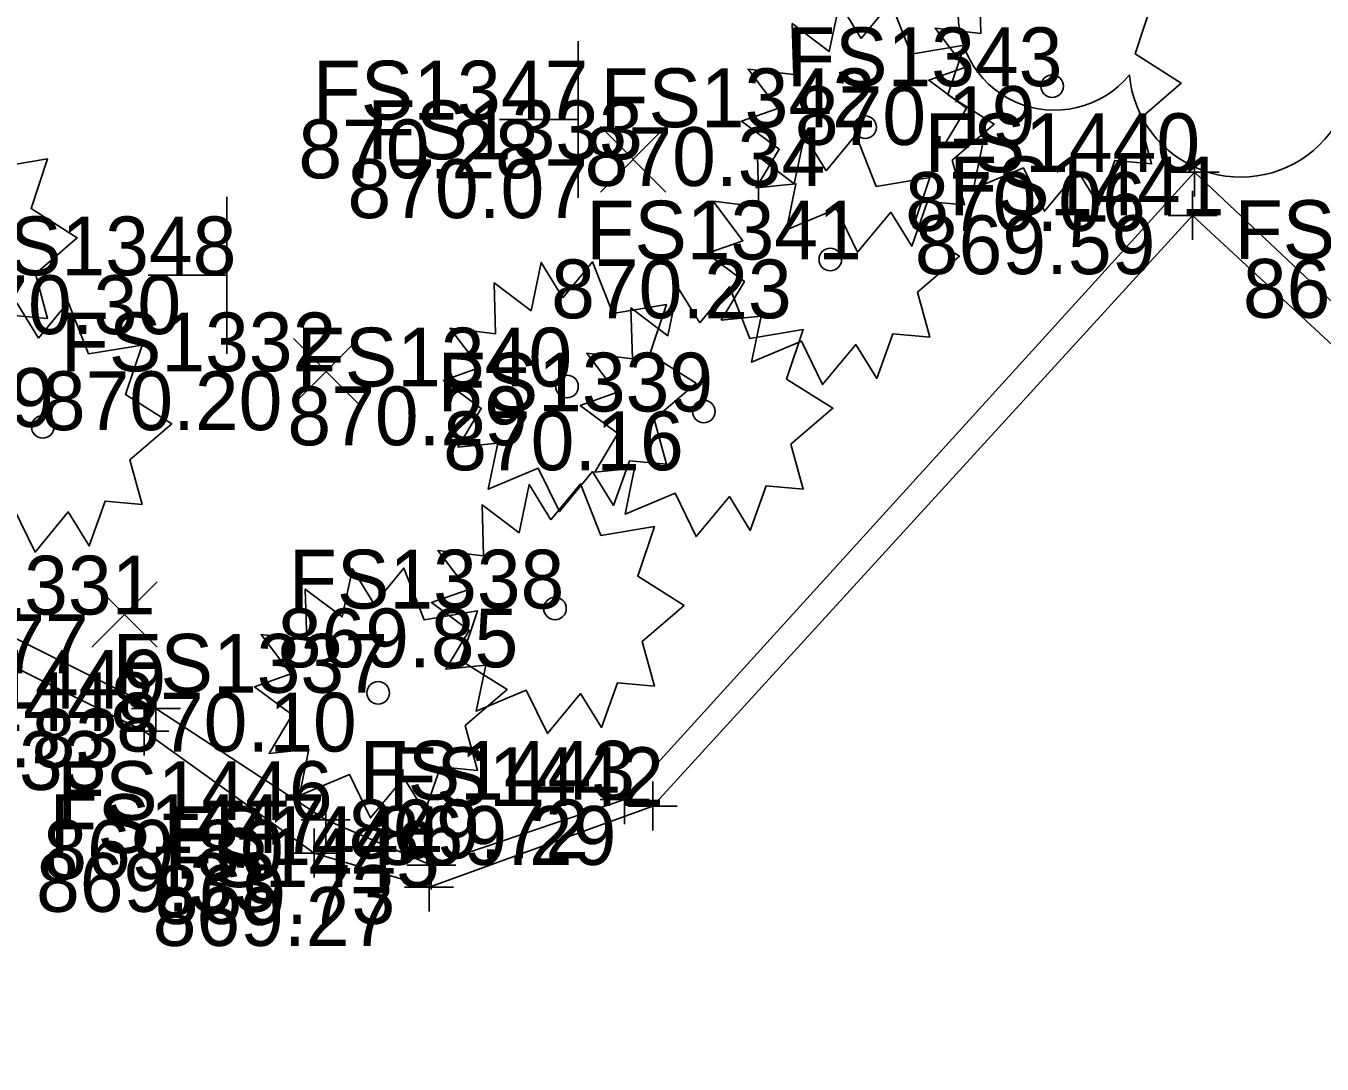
# Model space of a CAD drawing. Extents: x 1479420 to 1479833, y 379731 to 380103.
# Drawn here: x 1479616.34 to 1479642.79, y 379843.6 to 379864.79 of the extents above; entities that cross this region are included whole.
import ezdxf

# ---------------------------------------------------------------- set-up
doc = ezdxf.new("R2010")
doc.units = 0
for name, color, linetype in [('PV_X_Curb', 7, 'Continuous'), ('SN_X_Public', 7, 'Continuous'), ('SV_X_Random_Point', 7, 'Continuous'), ('SV_X_Shot_Marker', 7, 'Continuous'), ('SV_X_Text_Elevation', 7, 'Continuous'), ('SV_X_Text_Name', 7, 'Continuous'), ('VG_X_Cells', 7, 'Continuous')]:
    doc.layers.add(name, color=color, linetype=linetype)

msp = doc.modelspace()

# ---------------------------------------------------------------- linework, layer by layer
at = {"layer": 'PV_X_Curb'}
for points in [[(1479752.341, 379756.82), (1479734.895, 379773.493), (1479717.229, 379789.662), (1479699.298, 379806.401), (1479688.16, 379794.934), (1479685.526, 379793.897), (1479682.733, 379795.157), (1479681.263, 379797.549), (1479682.493, 379800.746), (1479693.462, 379811.911), (1479675.554, 379828.75), (1479655.832, 379847.057), (1479640.191, 379861.808), (1479628.558, 379849), (1479624.614, 379847.663), (1479622.46, 379848.585), (1479618.996, 379850.857), (1479611.825, 379854.437), (1479601.319, 379856.891), (1479590.521, 379858.038)], [(1479751.933, 379756.628), (1479734.447, 379772.976), (1479716.701, 379789.463), (1479699.4, 379805.742), (1479688.561, 379794.786), (1479685.717, 379793.294), (1479682.291, 379794.8), (1479680.73, 379797.254), (1479682.169, 379801.189), (1479692.652, 379811.907), (1479675.183, 379828.391), (1479655.51, 379846.682), (1479640.151, 379860.926), (1479629.134, 379848.869), (1479624.571, 379847.215), (1479622.228, 379847.911), (1479618.757, 379850.398), (1479611.519, 379853.97), (1479601.347, 379856.369), (1479590.364, 379857.442)]]:
    msp.add_lwpolyline(points, dxfattribs=at)
at = {"layer": 'SN_X_Public'}
for p, q in [((1479627.61, 379864.482), (1479627.61, 379861.282)), ((1479627.61, 379862.882), (1479626.01, 379862.882)), ((1479620.441, 379861.302), (1479620.441, 379858.102)), ((1479620.441, 379859.702), (1479618.841, 379859.702))]:
    msp.add_line(p, q, dxfattribs=at)
at = {"layer": 'SV_X_Random_Point'}
for p, q in [((1479628.067, 379861.402), (1479629.401, 379862.737)), ((1479628.067, 379862.737), (1479629.401, 379861.402)), ((1479621.802, 379857.075), (1479623.136, 379858.41)), ((1479621.802, 379858.41), (1479623.136, 379857.075)), ((1479617.687, 379852.111), (1479619.021, 379853.446)), ((1479617.687, 379853.446), (1479619.021, 379852.111))]:
    msp.add_line(p, q, dxfattribs=at)
at = {"layer": 'SV_X_Shot_Marker'}
for p, q in [((1479640.191, 379862.308), (1479640.191, 379861.308)), ((1479639.691, 379861.808), (1479640.691, 379861.808)), ((1479640.191, 379861.808), (1479640.191, 379861.808)), ((1479640.151, 379861.426), (1479640.151, 379860.426)), ((1479639.651, 379860.926), (1479640.651, 379860.926)), ((1479640.151, 379860.926), (1479640.151, 379860.926)), ((1479618.996, 379851.357), (1479618.996, 379850.357)), ((1479618.496, 379850.857), (1479619.496, 379850.857)), ((1479618.757, 379850.898), (1479618.757, 379849.898)), ((1479618.996, 379850.857), (1479618.996, 379850.857)), ((1479618.257, 379850.398), (1479619.257, 379850.398)), ((1479618.757, 379850.398), (1479618.757, 379850.398)), ((1479628.558, 379849.5), (1479628.558, 379848.5)), ((1479629.134, 379849.369), (1479629.134, 379848.369)), ((1479622.46, 379849.085), (1479622.46, 379848.085)), ((1479628.058, 379849), (1479629.058, 379849)), ((1479628.558, 379849), (1479628.558, 379849)), ((1479628.634, 379848.869), (1479629.634, 379848.869)), ((1479629.134, 379848.869), (1479629.134, 379848.869)), ((1479621.96, 379848.585), (1479622.96, 379848.585)), ((1479622.46, 379848.585), (1479622.46, 379848.585)), ((1479622.228, 379848.411), (1479622.228, 379847.411)), ((1479624.614, 379848.163), (1479624.614, 379847.163)), ((1479621.728, 379847.911), (1479622.728, 379847.911)), ((1479622.228, 379847.911), (1479622.228, 379847.911)), ((1479624.114, 379847.663), (1479625.114, 379847.663)), ((1479624.571, 379847.715), (1479624.571, 379846.715)), ((1479624.614, 379847.663), (1479624.614, 379847.663)), ((1479624.071, 379847.215), (1479625.071, 379847.215)), ((1479624.571, 379847.215), (1479624.571, 379847.215))]:
    msp.add_line(p, q, dxfattribs=at)
at = {"layer": 'VG_X_Cells'}
for points in [[(1479639.314, 379865.233), (1479638.975, 379864.222), (1479639.92, 379863.627), (1479639.064, 379862.892), (1479639.314, 379861.978), (1479638.56, 379862.047), (1479638.235, 379861.133), (1479637.807, 379861.825), (1479637.129, 379861.008), (1479636.7, 379861.895), (1479635.68, 379861.465), (1479635.872, 379862.407), (1479635.06, 379862.323), (1479635.534, 379863.113), (1479634.765, 379863.682), (1479635.504, 379863.945), (1479634.897, 379864.748), (1479635.829, 379864.638), (1479635.799, 379865.677)], [(1479633.385, 379864.535), (1479633.99, 379865.27), (1479634.405, 379864.216), (1479635.497, 379864.396), (1479635.158, 379863.385), (1479636.103, 379862.79), (1479635.247, 379862.055), (1479635.497, 379861.141), (1479634.743, 379861.21), (1479634.418, 379860.296), (1479633.99, 379860.988), (1479633.312, 379860.171), (1479632.883, 379861.058), (1479631.863, 379860.628), (1479632.055, 379861.57), (1479631.243, 379861.486), (1479631.717, 379862.276), (1479630.948, 379862.845), (1479631.687, 379863.108), (1479631.08, 379863.911), (1479632.012, 379863.801), (1479631.982, 379864.84), (1479632.735, 379864.271), (1479632.942, 379865.256), (1479633.385, 379864.535)], [(1479632.673, 379861.835), (1479633.278, 379862.57), (1479633.693, 379861.517), (1479634.785, 379861.697), (1479634.446, 379860.685), (1479635.391, 379860.09), (1479634.535, 379859.355), (1479634.785, 379858.442), (1479634.031, 379858.51), (1479633.706, 379857.597), (1479633.278, 379858.288), (1479632.6, 379857.472), (1479632.171, 379858.358), (1479631.151, 379857.928), (1479631.343, 379858.87), (1479630.531, 379858.787), (1479631.005, 379859.577), (1479630.236, 379860.145), (1479630.975, 379860.408), (1479630.368, 379861.212), (1479631.3, 379861.102), (1479631.27, 379862.14), (1479632.023, 379861.572), (1479632.23, 379862.557), (1479632.673, 379861.835)], [(1479615.694, 379861.896), (1479616.786, 379862.076), (1479616.447, 379861.065), (1479617.392, 379860.47), (1479616.536, 379859.735), (1479616.786, 379858.821), (1479616.032, 379858.89)], [(1479627.301, 379859.243), (1479627.906, 379859.978), (1479628.321, 379858.925), (1479629.413, 379859.105), (1479629.074, 379858.093), (1479630.019, 379857.498), (1479629.163, 379856.763), (1479629.413, 379855.85), (1479628.659, 379855.918), (1479628.334, 379855.005), (1479627.906, 379855.697), (1479627.228, 379854.88), (1479626.799, 379855.767), (1479625.779, 379855.337), (1479625.971, 379856.278), (1479625.159, 379856.195), (1479625.633, 379856.985), (1479624.864, 379857.553), (1479625.603, 379857.817), (1479624.996, 379858.62), (1479625.928, 379858.51), (1479625.898, 379859.548), (1479626.651, 379858.98), (1479626.858, 379859.965), (1479627.301, 379859.243)], [(1479630.092, 379858.733), (1479630.697, 379859.468), (1479631.112, 379858.415), (1479632.204, 379858.595), (1479631.865, 379857.583), (1479632.81, 379856.988), (1479631.954, 379856.253), (1479632.204, 379855.34), (1479631.45, 379855.408), (1479631.125, 379854.495), (1479630.697, 379855.187), (1479630.019, 379854.37), (1479629.59, 379855.257), (1479628.57, 379854.827), (1479628.762, 379855.768), (1479627.95, 379855.685), (1479628.424, 379856.475), (1479627.655, 379857.043), (1479628.394, 379857.307), (1479627.787, 379858.11), (1479628.719, 379858), (1479628.689, 379859.038), (1479629.442, 379858.47), (1479629.649, 379859.455), (1479630.092, 379858.733)], [(1479616.602, 379858.418), (1479617.207, 379859.153), (1479617.622, 379858.099), (1479618.714, 379858.279), (1479618.375, 379857.268), (1479619.32, 379856.673), (1479618.464, 379855.938), (1479618.714, 379855.024), (1479617.96, 379855.093), (1479617.635, 379854.179), (1479617.207, 379854.871), (1479616.529, 379854.054), (1479616.1, 379854.941)], [(1479616.159, 379859.139), (1479616.602, 379858.418)], [(1479627.056, 379854.711), (1479627.661, 379855.446), (1479628.076, 379854.393), (1479629.168, 379854.573), (1479628.829, 379853.561), (1479629.774, 379852.966), (1479628.918, 379852.231), (1479629.168, 379851.318), (1479628.414, 379851.386), (1479628.089, 379850.473), (1479627.661, 379851.164), (1479626.983, 379850.348), (1479626.554, 379851.234), (1479625.534, 379850.804), (1479625.726, 379851.746), (1479624.914, 379851.663), (1479625.388, 379852.453), (1479624.619, 379853.021), (1479625.358, 379853.284), (1479624.751, 379854.088), (1479625.683, 379853.978), (1479625.653, 379855.016), (1479626.406, 379854.448), (1479626.613, 379855.433), (1479627.056, 379854.711)], [(1479623.447, 379852.992), (1479624.052, 379853.727), (1479624.467, 379852.673), (1479625.559, 379852.853), (1479625.22, 379851.842), (1479626.165, 379851.247), (1479625.309, 379850.512), (1479625.559, 379849.598), (1479624.805, 379849.667), (1479624.48, 379848.753), (1479624.052, 379849.445), (1479623.374, 379848.628), (1479622.945, 379849.515), (1479621.925, 379849.085), (1479622.117, 379850.027), (1479621.305, 379849.943), (1479621.779, 379850.733), (1479621.01, 379851.302), (1479621.749, 379851.565), (1479621.142, 379852.368), (1479622.074, 379852.258), (1479622.044, 379853.297), (1479622.797, 379852.728), (1479623.004, 379853.713), (1479623.447, 379852.992)]]:
    msp.add_lwpolyline(points, dxfattribs=at)
for centre in [(1479637.286, 379863.562), (1479633.469, 379862.725), (1479632.757, 379860.025), (1479627.385, 379857.434), (1479630.176, 379856.924), (1479616.686, 379856.608), (1479627.14, 379852.901), (1479623.531, 379851.182)]:
    msp.add_circle(centre, 0.23, dxfattribs=at)
for centre, radius, start, end in [((1479637.338, 379865.046), 1.974, 96.1722, 320.5737), ((1479641.137, 379863.99), 2.284, 184.9476, 19.4572)]:
    msp.add_arc(centre, radius, start, end, dxfattribs=at)

# ---------------------------------------------------------------- texts
at = {"layer": 'SV_X_Text_Elevation'}
for s, p in [('870.19', (1479632.034, 379862.362)), ('870.28', (1479621.903, 379861.682)), ('870.34', (1479627.744, 379861.525)), ('870.07', (1479622.905, 379860.87)), ('870.06', (1479634.286, 379860.608)), ('869.59', (1479634.482, 379859.726)), ('870.23', (1479627.061, 379858.825)), ('869.81', (1479641.176, 379858.835)), ('870.30', (1479614.602, 379858.502)), ('870.20', (1479616.668, 379856.542)), ('870.29', (1479621.679, 379856.233)), ('870.16', (1479624.858, 379855.723)), ('869.85', (1479621.482, 379851.701)), ('869.77', (1479612.713, 379851.579)), ('870.10', (1479618.185, 379849.982)), ('869.83', (1479613.337, 379849.657)), ('869.33', (1479613.079, 379849.198)), ('869.72', (1479622.927, 379847.8)), ('869.29', (1479623.484, 379847.669)), ('869.80', (1479616.697, 379847.385)), ('869.33', (1479616.55, 379846.711)), ('869.73', (1479618.973, 379846.463)), ('869.27', (1479618.93, 379846.015))]:
    msp.add_text(s, height=1.2, dxfattribs=at).set_placement(p)
at = {"layer": 'SV_X_Text_Name'}
for s, p in [('FS1343', (1479631.874, 379863.562)), ('FS1347', (1479622.197, 379862.882)), ('FS1342', (1479628.066, 379862.725)), ('FS1333', (1479623.311, 379862.07)), ('FS1440', (1479634.683, 379861.808)), ('FS1441', (1479635.181, 379860.926)), ('FS1341', (1479627.779, 379860.025)), ('FS1352', (1479641.008, 379860.035)), ('FS1348', (1479615.018, 379859.702)), ('FS1332', (1479617.056, 379857.742)), ('FS1340', (1479621.869, 379857.433)), ('FS1339', (1479624.745, 379856.923)), ('FS1329', (1479611.293, 379856.608)), ('FS1331', (1479613.365, 379852.779)), ('FS1338', (1479621.709, 379852.901)), ('FS1337', (1479618.109, 379851.182)), ('FS1449', (1479613.583, 379850.857)), ('FS1448', (1479613.344, 379850.398)), ('FS1443', (1479623.154, 379849)), ('FS1442', (1479623.74, 379848.869)), ('FS1446', (1479616.981, 379848.585)), ('FS1447', (1479616.824, 379847.911)), ('FS1444', (1479619.22, 379847.663)), ('FS1445', (1479619.167, 379847.215))]:
    msp.add_text(s, height=1.2, dxfattribs=at).set_placement(p)

doc.saveas('drawing.dxf')
